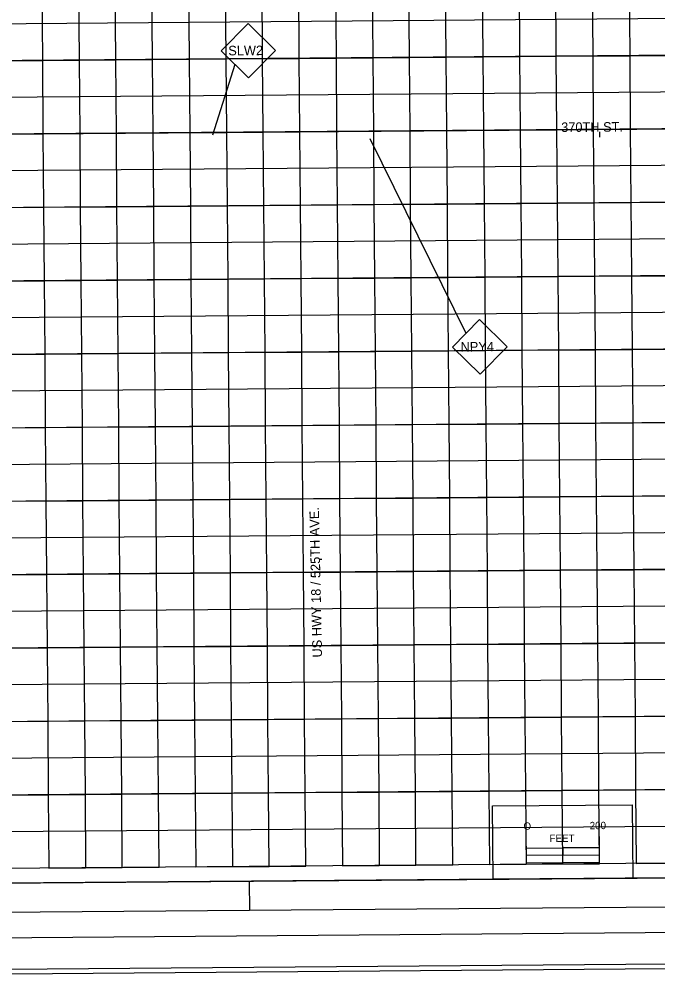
# Model space of a CAD drawing. Extents: x 11670159 to 11702568, y 9558247 to 9571922.
# Drawn here: x 11685781 to 11687520, y 9566402 to 9569018 of the extents above; entities that cross this region are included whole.
import ezdxf

# ---------------------------------------------------------------- set-up
doc = ezdxf.new("R2010")
doc.units = 0
for name, color, linetype in [('dsnCellElements', 7, 'Continuous'), ('dsnCellsScaleBlock', 7, 'Continuous'), ('dsnNonPlotable', 7, 'Continuous'), ('DsnShtHorizMidLine', 7, 'Continuous'), ('DsnShtInsideBorder', 7, 'Continuous'), ('DsnShtMajorGrid01', 7, 'Continuous'), ('DsnShtMajorGrid02', 7, 'Continuous'), ('DsnShtMajorGrid03', 7, 'Continuous'), ('DsnShtMajorGrid04', 7, 'Continuous'), ('DsnShtMajorGrid05', 7, 'Continuous'), ('DsnShtMajorGrid06', 7, 'Continuous'), ('DsnShtMajorGrid07', 7, 'Continuous'), ('DsnShtMajorGrid08', 7, 'Continuous'), ('DsnShtMajorGrid09', 7, 'Continuous'), ('DsnShtMajorGrid10', 7, 'Continuous'), ('DsnShtMajorGrid11', 7, 'Continuous'), ('DsnShtMajorGrid12', 7, 'Continuous'), ('DsnShtMinorGrid01', 7, 'Continuous'), ('DsnShtMinorGrid02', 7, 'Continuous'), ('DsnShtMinorGrid03', 7, 'Continuous'), ('DsnShtMinorGrid04', 7, 'Continuous'), ('DsnShtMinorGrid05', 7, 'Continuous'), ('DsnShtMinorGrid06', 7, 'Continuous'), ('DsnShtMinorGrid07', 7, 'Continuous'), ('DsnShtMinorGrid08', 7, 'Continuous'), ('DsnShtMinorGrid09', 7, 'Continuous'), ('DsnShtMinorGrid10', 7, 'Continuous'), ('DsnShtMinorGrid11', 7, 'Continuous'), ('DsnShtMinorGrid12', 7, 'Continuous'), ('DsnShtOutsideBorder', 7, 'Continuous'), ('DsnShtPlotShape', 7, 'Continuous'), ('dsnShtPlotShapeBatchPrint', 7, 'Continuous'), ('dsnTextFinalPlan', 7, 'Continuous'), ('hwyPlanSheetShape', 7, 'Continuous'), ('PvmtMrkngPrplCallout', 7, 'Continuous')]:
    doc.layers.add(name, color=color, linetype=linetype)

msp = doc.modelspace()

# ---------------------------------------------------------------- linework, layer by layer
at = {"layer": 'dsnCellElements'}
msp.add_lwpolyline([(11687070.3, 9566875.8), (11687450.3, 9566878.9), (11687451.9, 9566678.9), (11687071.9, 9566675.8)], close=True, dxfattribs=at)
at = {"layer": 'dsnCellsScaleBlock'}
msp.add_line((11687261.5, 9566721.4), (11687261.2, 9566761.4), dxfattribs=at)
msp.add_line((11687261.5, 9566721.4), (11687261.2, 9566761.4), dxfattribs=at)
for points in [[(11687071.9, 9566675.8), (11687070.3, 9566875.8), (11687450.3, 9566878.9), (11687451.9, 9566678.9)], [(11687261.4, 9566741.5), (11687361.4, 9566742.3), (11687361.2, 9566762.2), (11687261.2, 9566761.4)], [(11687161.5, 9566720.5), (11687261.5, 9566721.4), (11687261.4, 9566741.5), (11687161.4, 9566740.7)]]:
    msp.add_lwpolyline(points, close=True, dxfattribs=at)
for points in [[(11687161, 9566790.5), (11687161.5, 9566720.5), (11687361.5, 9566722.2), (11687361, 9566792.2)], [(11687161.2, 9566760.5), (11687361.2, 9566762.2)]]:
    msp.add_lwpolyline(points, dxfattribs=at)
at = {"layer": 'dsnNonPlotable'}
for p, q in [((11687361.4, 9568711.7), (11687361.5, 9568697.1)), ((11686600.1, 9567547.4), (11686605, 9567547.5))]:
    msp.add_line(p, q, dxfattribs=at)
msp.add_lwpolyline([(11684229.4, 9570693), (11690229.2, 9570741.4), (11690261.8, 9566701.6), (11684262, 9566653.2)], close=True, dxfattribs=at)
at = {"layer": 'DsnShtHorizMidLine'}
msp.add_line((11684110.5, 9568692), (11690380.3, 9568742.6), dxfattribs=at)
at = {"layer": 'DsnShtInsideBorder'}
msp.add_line((11686407.3, 9566670.5), (11686408, 9566590.5), dxfattribs=at)
at = {"layer": 'DsnShtMajorGrid01'}
for points in [[(11690394.8, 9566942.6), (11684125, 9566892.1)], [(11685660, 9566904.4), (11685860, 9566906.1), (11685861.6, 9566706.1), (11686061.6, 9566707.7), (11686060, 9566907.7), (11686260, 9566909.3), (11686261.6, 9566709.3), (11686461.6, 9566710.9), (11686460, 9566910.9), (11686660, 9566912.5), (11686661.6, 9566712.5), (11686861.6, 9566714.1), (11686860, 9566914.1), (11687059.9, 9566915.7), (11687061.6, 9566715.7), (11687261.6, 9566717.4), (11687259.9, 9566917.3), (11687459.9, 9566919), (11687461.5, 9566719), (11687661.5, 9566720.6)], [(11690396.5, 9566742.6), (11684126.7, 9566692.1)]]:
    msp.add_lwpolyline(points, dxfattribs=at)
at = {"layer": 'DsnShtMajorGrid02'}
for points in [[(11690393.2, 9567142.6), (11684123.4, 9567092.1)], [(11685658.4, 9567104.4), (11685858.4, 9567106), (11685860, 9566906.1), (11686060, 9566907.7), (11686058.4, 9567107.7), (11686258.4, 9567109.3), (11686260, 9566909.3), (11686460, 9566910.9), (11686458.4, 9567110.9), (11686658.3, 9567112.5), (11686660, 9566912.5), (11686860, 9566914.1), (11686858.3, 9567114.1), (11687058.3, 9567115.7), (11687059.9, 9566915.7), (11687259.9, 9566917.3), (11687258.3, 9567117.3), (11687458.3, 9567119), (11687459.9, 9566919), (11687659.9, 9566920.6)], [(11690394.8, 9566942.6), (11684125, 9566892.1)]]:
    msp.add_lwpolyline(points, dxfattribs=at)
at = {"layer": 'DsnShtMajorGrid03'}
for points in [[(11690391.6, 9567342.6), (11684121.8, 9567292)], [(11685656.8, 9567304.4), (11685856.8, 9567306), (11685858.4, 9567106), (11686058.4, 9567107.7), (11686056.8, 9567307.7), (11686256.7, 9567309.3), (11686258.4, 9567109.3), (11686458.4, 9567110.9), (11686456.7, 9567310.9), (11686656.7, 9567312.5), (11686658.3, 9567112.5), (11686858.3, 9567114.1), (11686856.7, 9567314.1), (11687056.7, 9567315.7), (11687058.3, 9567115.7), (11687258.3, 9567117.3), (11687256.7, 9567317.3), (11687456.7, 9567318.9), (11687458.3, 9567119), (11687658.3, 9567120.6)], [(11690393.2, 9567142.6), (11684123.4, 9567092.1)]]:
    msp.add_lwpolyline(points, dxfattribs=at)
at = {"layer": 'DsnShtMajorGrid04'}
for points in [[(11690390, 9567542.6), (11684120.2, 9567492)], [(11685655.2, 9567504.4), (11685855.1, 9567506), (11685856.8, 9567306), (11686056.8, 9567307.7), (11686055.1, 9567507.6), (11686255.1, 9567509.3), (11686256.7, 9567309.3), (11686456.7, 9567310.9), (11686455.1, 9567510.9), (11686655.1, 9567512.5), (11686656.7, 9567312.5), (11686856.7, 9567314.1), (11686855.1, 9567514.1), (11687055.1, 9567515.7), (11687056.7, 9567315.7), (11687256.7, 9567317.3), (11687255.1, 9567517.3), (11687455.1, 9567518.9), (11687456.7, 9567318.9), (11687656.7, 9567320.6)], [(11690391.6, 9567342.6), (11684121.8, 9567292)]]:
    msp.add_lwpolyline(points, dxfattribs=at)
at = {"layer": 'DsnShtMajorGrid05'}
for points in [[(11690388.4, 9567742.6), (11684118.6, 9567692)], [(11685653.5, 9567704.4), (11685853.5, 9567706), (11685855.1, 9567506), (11686055.1, 9567507.6), (11686053.5, 9567707.6), (11686253.5, 9567709.3), (11686255.1, 9567509.3), (11686455.1, 9567510.9), (11686453.5, 9567710.9), (11686653.5, 9567712.5), (11686655.1, 9567512.5), (11686855.1, 9567514.1), (11686853.5, 9567714.1), (11687053.5, 9567715.7), (11687055.1, 9567515.7), (11687255.1, 9567517.3), (11687253.5, 9567717.3), (11687453.5, 9567718.9), (11687455.1, 9567518.9), (11687655.1, 9567520.6)], [(11690390, 9567542.6), (11684120.2, 9567492)]]:
    msp.add_lwpolyline(points, dxfattribs=at)
at = {"layer": 'DsnShtMajorGrid06'}
for points in [[(11690386.8, 9567942.6), (11684117, 9567892)], [(11685651.9, 9567904.4), (11685851.9, 9567906), (11685853.5, 9567706), (11686053.5, 9567707.6), (11686051.9, 9567907.6), (11686251.9, 9567909.2), (11686253.5, 9567709.3), (11686453.5, 9567710.9), (11686451.9, 9567910.9), (11686651.9, 9567912.5), (11686653.5, 9567712.5), (11686853.5, 9567714.1), (11686851.9, 9567914.1), (11687051.9, 9567915.7), (11687053.5, 9567715.7), (11687253.5, 9567717.3), (11687251.9, 9567917.3), (11687451.9, 9567918.9), (11687453.5, 9567718.9), (11687653.5, 9567720.5)], [(11690388.4, 9567742.6), (11684118.6, 9567692)]]:
    msp.add_lwpolyline(points, dxfattribs=at)
at = {"layer": 'DsnShtMajorGrid07'}
for points in [[(11690385.2, 9568142.6), (11684115.4, 9568092)], [(11685650.3, 9568104.4), (11685850.3, 9568106), (11685851.9, 9567906), (11686051.9, 9567907.6), (11686050.3, 9568107.6), (11686250.3, 9568109.2), (11686251.9, 9567909.2), (11686451.9, 9567910.9), (11686450.3, 9568110.9), (11686650.3, 9568112.5), (11686651.9, 9567912.5), (11686851.9, 9567914.1), (11686850.3, 9568114.1), (11687050.3, 9568115.7), (11687051.9, 9567915.7), (11687251.9, 9567917.3), (11687250.3, 9568117.3), (11687450.3, 9568118.9), (11687451.9, 9567918.9), (11687651.9, 9567920.5)], [(11690386.8, 9567942.6), (11684117, 9567892)]]:
    msp.add_lwpolyline(points, dxfattribs=at)
at = {"layer": 'DsnShtMajorGrid08'}
for points in [[(11690383.5, 9568342.6), (11684113.7, 9568292)], [(11685648.7, 9568304.4), (11685848.7, 9568306), (11685850.3, 9568106), (11686050.3, 9568107.6), (11686048.7, 9568307.6), (11686248.7, 9568309.2), (11686250.3, 9568109.2), (11686450.3, 9568110.9), (11686448.7, 9568310.8), (11686648.7, 9568312.5), (11686650.3, 9568112.5), (11686850.3, 9568114.1), (11686848.7, 9568314.1), (11687048.7, 9568315.7), (11687050.3, 9568115.7), (11687250.3, 9568117.3), (11687248.6, 9568317.3), (11687448.6, 9568318.9), (11687450.3, 9568118.9), (11687650.2, 9568120.5)], [(11690385.2, 9568142.6), (11684115.4, 9568092)]]:
    msp.add_lwpolyline(points, dxfattribs=at)
at = {"layer": 'DsnShtMajorGrid09'}
for points in [[(11690381.9, 9568542.6), (11684112.1, 9568492)], [(11685647.1, 9568504.4), (11685847.1, 9568506), (11685848.7, 9568306), (11686048.7, 9568307.6), (11686047.1, 9568507.6), (11686247.1, 9568509.2), (11686248.7, 9568309.2), (11686448.7, 9568310.8), (11686447.1, 9568510.8), (11686647.1, 9568512.5), (11686648.7, 9568312.5), (11686848.7, 9568314.1), (11686847, 9568514.1), (11687047, 9568515.7), (11687048.7, 9568315.7), (11687248.6, 9568317.3), (11687247, 9568517.3), (11687447, 9568518.9), (11687448.6, 9568318.9), (11687648.6, 9568320.5)], [(11690383.5, 9568342.6), (11684113.7, 9568292)]]:
    msp.add_lwpolyline(points, dxfattribs=at)
at = {"layer": 'DsnShtMajorGrid10'}
for points in [[(11690380.3, 9568742.6), (11684110.5, 9568692)], [(11685645.5, 9568704.4), (11685845.5, 9568706), (11685847.1, 9568506), (11686047.1, 9568507.6), (11686045.5, 9568707.6), (11686245.5, 9568709.2), (11686247.1, 9568509.2), (11686447.1, 9568510.8), (11686445.4, 9568710.8), (11686645.4, 9568712.4), (11686647.1, 9568512.5), (11686847, 9568514.1), (11686845.4, 9568714.1), (11687045.4, 9568715.7), (11687047, 9568515.7), (11687247, 9568517.3), (11687245.4, 9568717.3), (11687445.4, 9568718.9), (11687447, 9568518.9), (11687647, 9568520.5)], [(11690381.9, 9568542.6), (11684112.1, 9568492)]]:
    msp.add_lwpolyline(points, dxfattribs=at)
at = {"layer": 'DsnShtMajorGrid11'}
for points in [[(11690378.7, 9568942.6), (11684108.9, 9568892)], [(11685643.9, 9568904.4), (11685843.9, 9568906), (11685845.5, 9568706), (11686045.5, 9568707.6), (11686043.8, 9568907.6), (11686243.8, 9568909.2), (11686245.5, 9568709.2), (11686445.4, 9568710.8), (11686443.8, 9568910.8), (11686643.8, 9568912.4), (11686645.4, 9568712.4), (11686845.4, 9568714.1), (11686843.8, 9568914.1), (11687043.8, 9568915.7), (11687045.4, 9568715.7), (11687245.4, 9568717.3), (11687243.8, 9568917.3), (11687443.8, 9568918.9), (11687445.4, 9568718.9), (11687645.4, 9568720.5)], [(11690380.3, 9568742.6), (11684110.5, 9568692)]]:
    msp.add_lwpolyline(points, dxfattribs=at)
at = {"layer": 'DsnShtMajorGrid12'}
for points in [[(11685842.2, 9569106), (11685843.9, 9568906), (11686043.8, 9568907.6), (11686042.2, 9569107.6)], [(11686242.2, 9569109.2), (11686243.8, 9568909.2), (11686443.8, 9568910.8), (11686442.2, 9569110.8)], [(11686642.2, 9569112.4), (11686643.8, 9568912.4), (11686843.8, 9568914.1), (11686842.2, 9569114)], [(11687042.2, 9569115.7), (11687043.8, 9568915.7), (11687243.8, 9568917.3), (11687242.2, 9569117.3)], [(11687442.2, 9569118.9), (11687443.8, 9568918.9), (11687643.8, 9568920.5)], [(11690378.7, 9568942.6), (11684108.9, 9568892)]]:
    msp.add_lwpolyline(points, dxfattribs=at)
at = {"layer": 'DsnShtMinorGrid01'}
for points in [[(11685760, 9566905.2), (11685960, 9566906.9), (11685961.6, 9566706.9), (11686161.6, 9566708.5), (11686160, 9566908.5), (11686360, 9566910.1), (11686361.6, 9566710.1), (11686561.6, 9566711.7), (11686560, 9566911.7), (11686760, 9566913.3), (11686761.6, 9566713.3), (11686961.6, 9566714.9), (11686959.9, 9566914.9), (11687159.9, 9566916.5), (11687161.6, 9566716.5), (11687361.5, 9566718.2), (11687359.9, 9566918.2), (11687559.9, 9566919.8)], [(11690260.6, 9566841.5), (11684260.8, 9566793.1)]]:
    msp.add_lwpolyline(points, dxfattribs=at)
at = {"layer": 'DsnShtMinorGrid02'}
for points in [[(11685758.4, 9567105.2), (11685958.4, 9567106.9), (11685960, 9566906.9), (11686160, 9566908.5), (11686158.4, 9567108.5), (11686358.4, 9567110.1), (11686360, 9566910.1), (11686560, 9566911.7), (11686558.3, 9567111.7), (11686758.3, 9567113.3), (11686760, 9566913.3), (11686959.9, 9566914.9), (11686958.3, 9567114.9), (11687158.3, 9567116.5), (11687159.9, 9566916.5), (11687359.9, 9566918.2), (11687358.3, 9567118.1), (11687558.3, 9567119.8)], [(11690259, 9567041.5), (11684259.2, 9566993.1)]]:
    msp.add_lwpolyline(points, dxfattribs=at)
at = {"layer": 'DsnShtMinorGrid03'}
for points in [[(11685756.8, 9567305.2), (11685956.8, 9567306.8), (11685958.4, 9567106.9), (11686158.4, 9567108.5), (11686156.7, 9567308.5), (11686356.7, 9567310.1), (11686358.4, 9567110.1), (11686558.3, 9567111.7), (11686556.7, 9567311.7), (11686756.7, 9567313.3), (11686758.3, 9567113.3), (11686958.3, 9567114.9), (11686956.7, 9567314.9), (11687156.7, 9567316.5), (11687158.3, 9567116.5), (11687358.3, 9567118.1), (11687356.7, 9567318.1), (11687556.7, 9567319.8)], [(11690257.4, 9567241.5), (11684257.6, 9567193.1)]]:
    msp.add_lwpolyline(points, dxfattribs=at)
at = {"layer": 'DsnShtMinorGrid04'}
for points in [[(11685755.1, 9567505.2), (11685955.1, 9567506.8), (11685956.8, 9567306.8), (11686156.7, 9567308.5), (11686155.1, 9567508.5), (11686355.1, 9567510.1), (11686356.7, 9567310.1), (11686556.7, 9567311.7), (11686555.1, 9567511.7), (11686755.1, 9567513.3), (11686756.7, 9567313.3), (11686956.7, 9567314.9), (11686955.1, 9567514.9), (11687155.1, 9567516.5), (11687156.7, 9567316.5), (11687356.7, 9567318.1), (11687355.1, 9567518.1), (11687555.1, 9567519.7)], [(11690255.8, 9567441.5), (11684256, 9567393.1)]]:
    msp.add_lwpolyline(points, dxfattribs=at)
at = {"layer": 'DsnShtMinorGrid05'}
for points in [[(11685753.5, 9567705.2), (11685953.5, 9567706.8), (11685955.1, 9567506.8), (11686155.1, 9567508.5), (11686153.5, 9567708.4), (11686353.5, 9567710.1), (11686355.1, 9567510.1), (11686555.1, 9567511.7), (11686553.5, 9567711.7), (11686753.5, 9567713.3), (11686755.1, 9567513.3), (11686955.1, 9567514.9), (11686953.5, 9567714.9), (11687153.5, 9567716.5), (11687155.1, 9567516.5), (11687355.1, 9567518.1), (11687353.5, 9567718.1), (11687553.5, 9567719.7)], [(11690254.2, 9567641.5), (11684254.4, 9567593.1)]]:
    msp.add_lwpolyline(points, dxfattribs=at)
at = {"layer": 'DsnShtMinorGrid06'}
for points in [[(11685751.9, 9567905.2), (11685951.9, 9567906.8), (11685953.5, 9567706.8), (11686153.5, 9567708.4), (11686151.9, 9567908.4), (11686351.9, 9567910.1), (11686353.5, 9567710.1), (11686553.5, 9567711.7), (11686551.9, 9567911.7), (11686751.9, 9567913.3), (11686753.5, 9567713.3), (11686953.5, 9567714.9), (11686951.9, 9567914.9), (11687151.9, 9567916.5), (11687153.5, 9567716.5), (11687353.5, 9567718.1), (11687351.9, 9567918.1), (11687551.9, 9567919.7)], [(11690252.6, 9567841.5), (11684252.8, 9567793.1)]]:
    msp.add_lwpolyline(points, dxfattribs=at)
at = {"layer": 'DsnShtMinorGrid07'}
for points in [[(11685750.3, 9568105.2), (11685950.3, 9568106.8), (11685951.9, 9567906.8), (11686151.9, 9567908.4), (11686150.3, 9568108.4), (11686350.3, 9568110), (11686351.9, 9567910.1), (11686551.9, 9567911.7), (11686550.3, 9568111.7), (11686750.3, 9568113.3), (11686751.9, 9567913.3), (11686951.9, 9567914.9), (11686950.3, 9568114.9), (11687150.3, 9568116.5), (11687151.9, 9567916.5), (11687351.9, 9567918.1), (11687350.3, 9568118.1), (11687550.3, 9568119.7)], [(11690251, 9568041.5), (11684251.2, 9567993.1)]]:
    msp.add_lwpolyline(points, dxfattribs=at)
at = {"layer": 'DsnShtMinorGrid08'}
for points in [[(11685748.7, 9568305.2), (11685948.7, 9568306.8), (11685950.3, 9568106.8), (11686150.3, 9568108.4), (11686148.7, 9568308.4), (11686348.7, 9568310), (11686350.3, 9568110), (11686550.3, 9568111.7), (11686548.7, 9568311.7), (11686748.7, 9568313.3), (11686750.3, 9568113.3), (11686950.3, 9568114.9), (11686948.7, 9568314.9), (11687148.7, 9568316.5), (11687150.3, 9568116.5), (11687350.3, 9568118.1), (11687348.6, 9568318.1), (11687548.6, 9568319.7)], [(11690249.4, 9568241.5), (11684249.6, 9568193.1)]]:
    msp.add_lwpolyline(points, dxfattribs=at)
at = {"layer": 'DsnShtMinorGrid09'}
for points in [[(11685747.1, 9568505.2), (11685947.1, 9568506.8), (11685948.7, 9568306.8), (11686148.7, 9568308.4), (11686147.1, 9568508.4), (11686347.1, 9568510), (11686348.7, 9568310), (11686548.7, 9568311.7), (11686547.1, 9568511.6), (11686747.1, 9568513.3), (11686748.7, 9568313.3), (11686948.7, 9568314.9), (11686947, 9568514.9), (11687147, 9568516.5), (11687148.7, 9568316.5), (11687348.6, 9568318.1), (11687347, 9568518.1), (11687547, 9568519.7)], [(11690247.7, 9568441.5), (11684247.9, 9568393.1)]]:
    msp.add_lwpolyline(points, dxfattribs=at)
at = {"layer": 'DsnShtMinorGrid10'}
for points in [[(11685745.5, 9568705.2), (11685945.5, 9568706.8), (11685947.1, 9568506.8), (11686147.1, 9568508.4), (11686145.5, 9568708.4), (11686345.4, 9568710), (11686347.1, 9568510), (11686547.1, 9568511.6), (11686545.4, 9568711.6), (11686745.4, 9568713.3), (11686747.1, 9568513.3), (11686947, 9568514.9), (11686945.4, 9568714.9), (11687145.4, 9568716.5), (11687147, 9568516.5), (11687347, 9568518.1), (11687345.4, 9568718.1), (11687545.4, 9568719.7)], [(11690246.1, 9568641.5), (11684246.3, 9568593.1)]]:
    msp.add_lwpolyline(points, dxfattribs=at)
at = {"layer": 'DsnShtMinorGrid11'}
for points in [[(11685743.9, 9568905.2), (11685943.8, 9568906.8), (11685945.5, 9568706.8), (11686145.5, 9568708.4), (11686143.8, 9568908.4), (11686343.8, 9568910), (11686345.4, 9568710), (11686545.4, 9568711.6), (11686543.8, 9568911.6), (11686743.8, 9568913.2), (11686745.4, 9568713.3), (11686945.4, 9568714.9), (11686943.8, 9568914.9), (11687143.8, 9568916.5), (11687145.4, 9568716.5), (11687345.4, 9568718.1), (11687343.8, 9568918.1), (11687543.8, 9568919.7)], [(11690244.5, 9568841.5), (11684244.7, 9568793.1)]]:
    msp.add_lwpolyline(points, dxfattribs=at)
at = {"layer": 'DsnShtMinorGrid12'}
for points in [[(11685942.2, 9569106.8), (11685943.8, 9568906.8), (11686143.8, 9568908.4), (11686142.2, 9569108.4)], [(11686342.2, 9569110), (11686343.8, 9568910), (11686543.8, 9568911.6), (11686542.2, 9569111.6)], [(11686742.2, 9569113.2), (11686743.8, 9568913.2), (11686943.8, 9568914.9), (11686942.2, 9569114.9)], [(11687142.2, 9569116.5), (11687143.8, 9568916.5), (11687343.8, 9568918.1), (11687342.2, 9569118.1)], [(11690242.9, 9569041.5), (11684243.1, 9568993.1), (11684242.3, 9569093.1)]]:
    msp.add_lwpolyline(points, dxfattribs=at)
at = {"layer": 'DsnShtOutsideBorder'}
msp.add_line((11684866.8, 9566658), (11687859.9, 9566682.2), dxfattribs=at)
msp.add_lwpolyline([(11684094.4, 9570691.9), (11690364.2, 9570742.5), (11690397.4, 9566622.6), (11684127.6, 9566572.1)], close=True, dxfattribs=at)
at = {"layer": 'DsnShtPlotShape'}
msp.add_lwpolyline([(11683828.5, 9570801.8), (11690628.3, 9570856.6), (11690663.8, 9566456.8), (11683864, 9566401.9)], close=True, dxfattribs=at)
at = {"layer": 'dsnShtPlotShapeBatchPrint'}
msp.add_lwpolyline([(11683907.6, 9570802.4), (11690549.2, 9570856), (11690584.6, 9566469.3), (11683943, 9566415.7)], close=True, dxfattribs=at)
at = {"layer": 'hwyPlanSheetShape'}
msp.add_lwpolyline([(11683998.8, 9570760.1), (11690458.6, 9570812.2), (11690493, 9566554), (11684033.2, 9566501.9)], close=True, dxfattribs=at)
at = {"layer": 'PvmtMrkngPrplCallout'}
for p, q in [((11686368.2, 9568895.1), (11686307.1, 9568702.2)), ((11686998.1, 9568162.6), (11686736.8, 9568692.6))]:
    msp.add_line(p, q, dxfattribs=at)
for points in [[(11686330.8, 9568932), (11686404.4, 9569006.8), (11686479.3, 9568933.2), (11686405.6, 9568858.3)], [(11686961.3, 9568125.1), (11687034.9, 9568200), (11687109.8, 9568126.3), (11687036.1, 9568051.5)]]:
    msp.add_lwpolyline(points, close=True, dxfattribs=at)

# ---------------------------------------------------------------- texts
at = {"layer": 'dsnCellsScaleBlock'}
for s, p in [('O', (11687154.3, 9566810.5)), ('O', (11687154.3, 9566810.5)), ('200', (11687334.7, 9566812)), ('FEET', (11687225.2, 9566777.1))]:
    msp.add_text(s, height=20, rotation=0.4622, dxfattribs=at).set_placement(p)
at = {"layer": 'dsnTextFinalPlan'}
for s, rotation, p in [('370TH ST.', 0.374, (11687257.2, 9568711)), ('US HWY 18 / 525TH AVE.', 91.2146, (11686605.8, 9567280))]:
    msp.add_text(s, height=26, rotation=rotation, dxfattribs=at).set_placement(p)
at = {"layer": 'PvmtMrkngPrplCallout'}
for s, p in [('SLW2', (11686350.4, 9568919.6)), ('NPY4', (11686983.1, 9568112.8))]:
    msp.add_text(s, height=26, rotation=0.4622, dxfattribs=at).set_placement(p)

doc.saveas('drawing.dxf')
